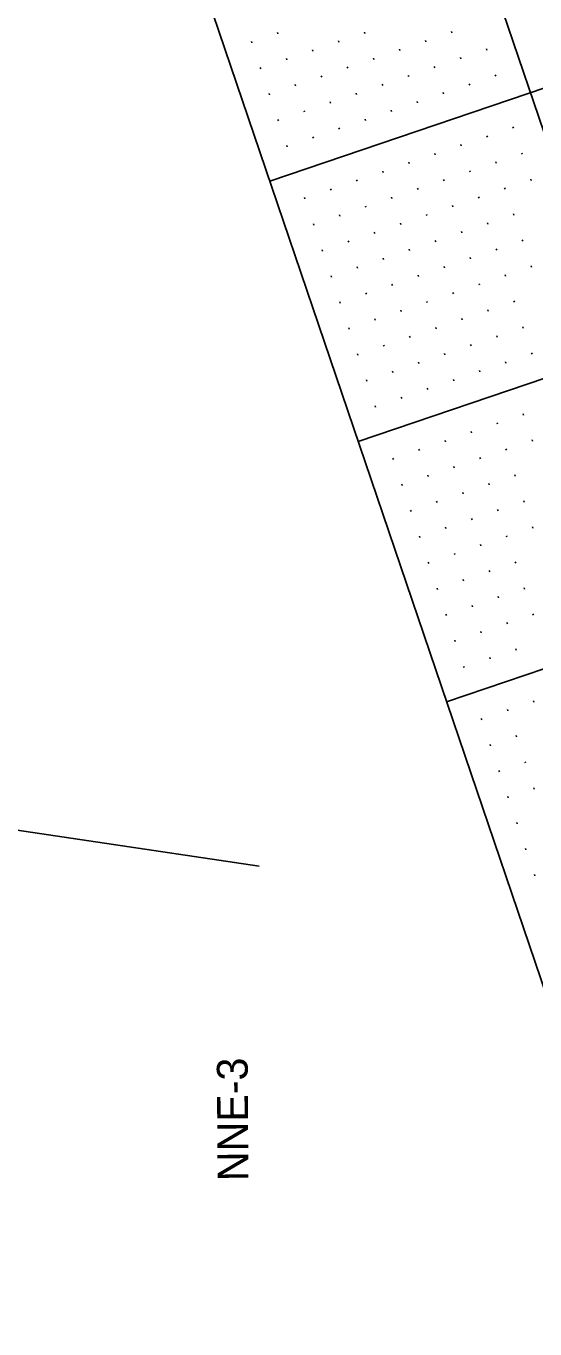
# Model space of a CAD drawing. Extents: x 2150318 to 2152065, y 143281 to 145371.
# Drawn here: x 2150900 to 2150992.5, y 144795.4 to 145032.3 of the extents above; entities that cross this region are included whole.
import ezdxf

# ---------------------------------------------------------------- set-up
doc = ezdxf.new("R2010")
doc.units = 0
for name, color, linetype in [('PR_Align_Service_B_Label', 7, 'Continuous'), ('PR_Align_Service_B_Leader', 7, 'Continuous'), ('SHT_Profile_Grid_Major', 7, 'Continuous'), ('SHT_Profile_Grid_Minor', 7, 'Continuous'), ('SHT_Sheet_Border', 7, 'Continuous')]:
    doc.layers.add(name, color=color, linetype=linetype)

msp = doc.modelspace()

# ---------------------------------------------------------------- linework, layer by layer
at = {"layer": 'PR_Align_Service_B_Leader'}
msp.add_lwpolyline([(2150942.37, 144879.57), (2150849.44, 144893.37), (2150810.36, 145008.6)], dxfattribs=at)
at = {"layer": 'SHT_Profile_Grid_Major'}
for p, q in [((2151453.47, 143658.9), (2150947.48, 145150.41)), ((2151323.1, 145132.64), (2150944.3, 145004.14)), ((2151410.19, 145109.39), (2150960.37, 144956.79)), ((2151426.25, 145062.04), (2150976.43, 144909.44))]:
    msp.add_line(p, q, dxfattribs=at)
at = {"layer": 'SHT_Profile_Grid_Minor'}
for p, q in [((2150941.05, 145029.3), (2150940.97, 145029.54)), ((2150945.78, 145030.91), (2150945.7, 145031.14)), ((2150956.86, 145029.38), (2150956.78, 145029.62)), ((2150961.59, 145030.99), (2150961.51, 145031.23)), ((2150972.67, 145029.47), (2150972.59, 145029.7)), ((2150977.4, 145031.07), (2150977.32, 145031.31)), ((2150952.12, 145027.78), (2150952.04, 145028.01)), ((2150967.93, 145027.86), (2150967.85, 145028.1)), ((2150983.74, 145027.95), (2150983.66, 145028.18)), ((2150942.65, 145024.56), (2150942.57, 145024.8)), ((2150947.39, 145026.17), (2150947.31, 145026.41)), ((2150958.46, 145024.65), (2150958.38, 145024.89)), ((2150963.2, 145026.25), (2150963.12, 145026.49)), ((2150974.27, 145024.73), (2150974.19, 145024.97)), ((2150979.01, 145026.34), (2150978.93, 145026.58)), ((2150953.73, 145023.04), (2150953.65, 145023.28)), ((2150969.54, 145023.13), (2150969.46, 145023.36)), ((2150985.35, 145023.21), (2150985.27, 145023.45)), ((2150944.26, 145019.83), (2150944.18, 145020.07)), ((2150948.99, 145021.44), (2150948.91, 145021.67)), ((2150960.07, 145019.91), (2150959.99, 145020.15)), ((2150964.81, 145021.52), (2150964.72, 145021.76)), ((2150975.88, 145020), (2150975.8, 145020.23)), ((2150980.62, 145021.6), (2150980.54, 145021.84)), ((2150955.34, 145018.31), (2150955.25, 145018.54)), ((2150971.15, 145018.39), (2150971.07, 145018.63)), ((2150945.87, 145015.09), (2150945.78, 145015.33)), ((2150950.6, 145016.7), (2150950.52, 145016.94)), ((2150961.68, 145015.18), (2150961.6, 145015.42)), ((2150966.41, 145016.78), (2150966.33, 145017.02)), ((2150956.94, 145013.57), (2150956.86, 145013.81)), ((2150988.56, 145013.74), (2150988.48, 145013.98)), ((2150947.47, 145010.36), (2150947.39, 145010.6)), ((2150952.21, 145011.97), (2150952.13, 145012.2)), ((2150979.09, 145010.53), (2150979.01, 145010.76)), ((2150983.83, 145012.13), (2150983.75, 145012.37)), ((2150974.36, 145008.92), (2150974.28, 145009.16)), ((2150990.17, 145009.01), (2150990.09, 145009.24)), ((2150964.89, 145005.71), (2150964.81, 145005.95)), ((2150969.62, 145007.31), (2150969.54, 145007.55)), ((2150980.7, 145005.79), (2150980.62, 145006.03)), ((2150985.44, 145007.4), (2150985.35, 145007.64)), ((2150960.15, 145004.1), (2150960.07, 145004.34)), ((2150975.97, 145004.19), (2150975.88, 145004.42)), ((2150991.78, 145004.27), (2150991.7, 145004.51)), ((2150950.68, 145000.89), (2150950.6, 145001.13)), ((2150955.42, 145002.5), (2150955.34, 145002.73)), ((2150966.5, 145000.97), (2150966.42, 145001.21)), ((2150971.23, 145002.58), (2150971.15, 145002.82)), ((2150982.31, 145001.06), (2150982.23, 145001.29)), ((2150987.04, 145002.66), (2150986.96, 145002.9)), ((2150961.76, 144999.37), (2150961.68, 144999.6)), ((2150977.57, 144999.45), (2150977.49, 144999.69)), ((2150952.29, 144996.15), (2150952.21, 144996.39)), ((2150957.03, 144997.76), (2150956.95, 144998)), ((2150968.1, 144996.24), (2150968.02, 144996.48)), ((2150972.84, 144997.85), (2150972.76, 144998.08)), ((2150983.91, 144996.32), (2150983.83, 144996.56)), ((2150988.65, 144997.93), (2150988.57, 144998.17)), ((2150963.37, 144994.63), (2150963.29, 144994.87)), ((2150979.18, 144994.72), (2150979.1, 144994.95)), ((2150953.9, 144991.42), (2150953.82, 144991.66)), ((2150958.63, 144993.03), (2150958.55, 144993.26)), ((2150969.71, 144991.5), (2150969.63, 144991.74)), ((2150974.44, 144993.11), (2150974.36, 144993.35)), ((2150985.52, 144991.59), (2150985.44, 144991.82)), ((2150990.25, 144993.19), (2150990.17, 144993.43)), ((2150964.97, 144989.9), (2150964.89, 144990.13)), ((2150980.78, 144989.98), (2150980.7, 144990.22)), ((2150955.5, 144986.68), (2150955.42, 144986.92)), ((2150960.24, 144988.29), (2150960.16, 144988.53)), ((2150971.31, 144986.77), (2150971.23, 144987.01)), ((2150976.05, 144988.38), (2150975.97, 144988.61)), ((2150987.13, 144986.85), (2150987.05, 144987.09)), ((2150991.86, 144988.46), (2150991.78, 144988.7)), ((2150966.58, 144985.16), (2150966.5, 144985.4)), ((2150982.39, 144985.25), (2150982.31, 144985.48)), ((2150957.11, 144981.95), (2150957.03, 144982.19)), ((2150961.84, 144983.56), (2150961.76, 144983.79)), ((2150972.92, 144982.03), (2150972.84, 144982.27)), ((2150977.66, 144983.64), (2150977.58, 144983.88)), ((2150988.73, 144982.12), (2150988.65, 144982.35)), ((2150968.19, 144980.43), (2150968.11, 144980.66)), ((2150984, 144980.51), (2150983.92, 144980.75)), ((2150958.72, 144977.22), (2150958.64, 144977.45)), ((2150963.45, 144978.82), (2150963.37, 144979.06)), ((2150974.53, 144977.3), (2150974.45, 144977.54)), ((2150979.26, 144978.91), (2150979.18, 144979.14)), ((2150990.34, 144977.38), (2150990.26, 144977.62)), ((2150969.79, 144975.69), (2150969.71, 144975.93)), ((2150985.6, 144975.78), (2150985.52, 144976.01)), ((2150960.32, 144972.48), (2150960.24, 144972.72)), ((2150965.06, 144974.09), (2150964.98, 144974.32)), ((2150976.13, 144972.56), (2150976.05, 144972.8)), ((2150980.87, 144974.17), (2150980.79, 144974.41)), ((2150991.94, 144972.65), (2150991.86, 144972.88)), ((2150971.4, 144970.96), (2150971.32, 144971.19)), ((2150987.21, 144971.04), (2150987.13, 144971.28)), ((2150961.93, 144967.75), (2150961.85, 144967.98)), ((2150966.66, 144969.35), (2150966.58, 144969.59)), ((2150977.74, 144967.83), (2150977.66, 144968.07)), ((2150982.47, 144969.44), (2150982.39, 144969.67)), ((2150973, 144966.22), (2150972.92, 144966.46)), ((2150963.53, 144963.01), (2150963.45, 144963.25)), ((2150968.27, 144964.62), (2150968.19, 144964.85)), ((2150990.42, 144961.57), (2150990.34, 144961.81)), ((2150980.95, 144958.36), (2150980.87, 144958.6)), ((2150985.69, 144959.97), (2150985.61, 144960.2)), ((2150976.22, 144956.75), (2150976.14, 144956.99)), ((2150992.03, 144956.84), (2150991.95, 144957.07)), ((2150966.75, 144953.54), (2150966.67, 144953.78)), ((2150971.48, 144955.15), (2150971.4, 144955.38)), ((2150982.56, 144953.62), (2150982.48, 144953.86)), ((2150987.29, 144955.23), (2150987.21, 144955.47)), ((2150977.82, 144952.02), (2150977.74, 144952.25)), ((2150968.35, 144948.81), (2150968.27, 144949.04)), ((2150973.09, 144950.41), (2150973.01, 144950.65)), ((2150984.16, 144948.89), (2150984.08, 144949.13)), ((2150988.9, 144950.5), (2150988.82, 144950.73)), ((2150979.43, 144947.28), (2150979.35, 144947.52)), ((2150969.96, 144944.07), (2150969.88, 144944.31)), ((2150974.69, 144945.68), (2150974.61, 144945.91)), ((2150985.77, 144944.15), (2150985.69, 144944.39)), ((2150990.51, 144945.76), (2150990.43, 144946)), ((2150981.04, 144942.55), (2150980.96, 144942.78)), ((2150971.57, 144939.34), (2150971.49, 144939.57)), ((2150976.3, 144940.94), (2150976.22, 144941.18)), ((2150987.38, 144939.42), (2150987.3, 144939.66)), ((2150992.11, 144941.03), (2150992.03, 144941.26)), ((2150982.64, 144937.81), (2150982.56, 144938.05)), ((2150973.17, 144934.6), (2150973.09, 144934.84)), ((2150977.91, 144936.21), (2150977.83, 144936.44)), ((2150988.98, 144934.68), (2150988.9, 144934.92)), ((2150984.25, 144933.08), (2150984.17, 144933.31)), ((2150974.78, 144929.87), (2150974.7, 144930.1)), ((2150979.51, 144931.47), (2150979.43, 144931.71)), ((2150990.59, 144929.95), (2150990.51, 144930.19)), ((2150985.86, 144928.34), (2150985.77, 144928.58)), ((2150976.39, 144925.13), (2150976.3, 144925.37)), ((2150981.12, 144926.74), (2150981.04, 144926.97)), ((2150992.2, 144925.21), (2150992.12, 144925.45)), ((2150987.46, 144923.61), (2150987.38, 144923.85)), ((2150977.99, 144920.4), (2150977.91, 144920.63)), ((2150982.73, 144922), (2150982.65, 144922.24)), ((2150989.07, 144918.87), (2150988.99, 144919.11)), ((2150979.6, 144915.66), (2150979.52, 144915.9)), ((2150984.33, 144917.27), (2150984.25, 144917.5)), ((2150992.28, 144909.4), (2150992.2, 144909.64)), ((2150982.81, 144906.19), (2150982.73, 144906.43)), ((2150987.55, 144907.8), (2150987.47, 144908.03)), ((2150984.42, 144901.46), (2150984.34, 144901.69)), ((2150989.15, 144903.06), (2150989.07, 144903.3)), ((2150986.02, 144896.72), (2150985.94, 144896.96)), ((2150990.76, 144898.33), (2150990.68, 144898.56)), ((2150987.63, 144891.99), (2150987.55, 144892.22)), ((2150992.36, 144893.59), (2150992.28, 144893.83)), ((2150989.24, 144887.25), (2150989.16, 144887.49)), ((2150990.84, 144882.52), (2150990.76, 144882.75)), ((2150992.45, 144877.78), (2150992.37, 144878.02))]:
    msp.add_line(p, q, dxfattribs=at)
at = {"layer": 'SHT_Sheet_Border'}
msp.add_line((2151406.12, 143642.84), (2150900.13, 145134.35), dxfattribs=at)

# ---------------------------------------------------------------- texts
at = {"layer": 'PR_Align_Service_B_Label'}
msp.add_text('NNE-3', height=5.6, rotation=90.3443, dxfattribs=at).set_placement((2150940.41, 144822.3))

doc.saveas('drawing.dxf')
